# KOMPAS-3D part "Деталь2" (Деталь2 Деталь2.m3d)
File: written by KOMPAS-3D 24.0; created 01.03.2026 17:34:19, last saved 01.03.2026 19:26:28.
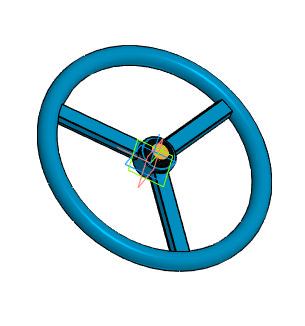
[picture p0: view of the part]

Document properties: Автор: R2D2; Полное имя файла: E:\Работа\Зайцев\GVWR3131M-2W-F-S Задвижка клиновая с выдвижным штоком DN.ru Ду50-200 Ру63\DN80\исходные материалы\Деталь2 Деталь2.m3d

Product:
- Body: Твердое тело1  | qty 1
    Масса: 4.922929
- Part/product: Деталь2
    Масса: 4.922929
    additional columns: Типовые

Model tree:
1. Твердое тело1  (labels: Твердое тело1)
2. Эскиз:1
3. Элемент выдавливания:1
     Расстояние 1 = 100
4. Эскиз:2
5. Элемент вращения:1
     Угол 1 = 360
6. Элемент выдавливания:2  (with: Грань.Элемент выдавливания:1, Грань.Элемент вращения:1)
     Расстояние 2 = 77.9664
7. Массив по концентрической сетке:1  (with: Элемент выдавливания:2)  (labels: Грань.Твердое тело1)  (3 pattern instances)
     Шаг 2 = 360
